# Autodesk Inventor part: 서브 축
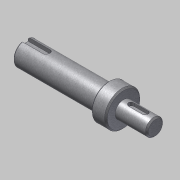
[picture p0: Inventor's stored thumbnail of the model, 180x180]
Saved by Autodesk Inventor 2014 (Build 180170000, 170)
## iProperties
Created: 2016-04
Part Number: 서브 축
Document SubType Name: Modeling
Designer: mdu
Density: 1 g/cm^3
Mass: 19.9624 g
Surface Area: 57.7178 cm^2
Volume: 19.9624 cm^3
Material: 강철, 연강
Appearance: 금속-강(스테인리스, 브러시됨)
Author: mdu
Revision Number: 1
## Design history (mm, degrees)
sketch "스케치1"
  geometry: L1 (-16.331, 0)-(-108.831, 0); L2 (-16.331, 0)-(-16.331, -6); L3 (-16.331, -6)-(-38.831, -6); L4 (-38.831, -12.5)-(-46.5, -12.5); L5 (-46.5, -8.5)-(-108.831, -8.5); L6 (-108.831, -8.5)-(-108.831, 0); L7 (-46.5, -8.5)-(-46.5, -12.5); L8 (-38.831, -6)-(-38.831, -12.5); L9 (-46.5, 12.249)-(-46.5, -12.249) reference; L10 (-38.831, -17)-(-38.831, 17) reference; 2 further points
  constraints: 17 end point, 4 perpendicular, 2 collinear, 2 parallel, 1 horizontal, 1 midpoint, 1 point on line
  dimensions: "d1" = 12 diameter of L3 L1; "d2" = 25 diameter of L4 L1; "d3" = 17 diameter of L5 L1; "d18" = 22.5 distance of L2.end L3.end; "d20" = 70 distance between parallel lines of L6 L8; "d21" = 7.66872 distance of L4.start L4.end (derived)
revolve "회전1" sketch "스케치1" stored, may be unused: angle "d5" = 90 deg
chamfer "모따기1" distance "d6" = 1; stored, may be unused: second distance "d7" = 2, angle "d8" = 45 deg
node "작업 평면1"
sketch "스케치2"
  geometry: L1 (11.25, 5)-(11.25, -5) reference; L2 (-5.75, -2)-(4.25, -2); L3 (4.25, 2)-(-5.75, 2); A1 r 2 centre (4.25, 0) between (4.25, -2) and (4.25, 2); A2 r 2 centre (-5.75, 0) between (-5.75, 2) and (-5.75, -2); 2 further points
  constraints: 4 end point, 4 point on circle, 4 tangent, 2 centre point, 1 horizontal alignment, 1 midpoint, 1 parallel, 1 perpendicular
  dimensions: "d9" = 4 distance between parallel lines of L2 L3; "d10" = 14 dimension on A1 A2; "d11" = 5 distance edge to line of A1 L1
extrude "돌출1" cut sketch "스케치2" distance "d12" = 2.5; taper "d13" = 0 deg
node "작업 평면2"
sketch "스케치3"
  geometry: L1 (-31.166, -7.5)-(-31.166, 7.5) reference; L2 (-31.166, 2.5)-(-15.666, 2.5); L3 (-15.666, -2.5)-(-31.166, -2.5); A1 r 2.5 centre (-15.666, 0) between (-15.666, -2.5) and (-15.666, 2.5); 2 further points
  constraints: 4 end point, 2 perpendicular, 2 point on circle, 2 point on line, 2 tangent, 1 centre point, 1 horizontal alignment, 1 midpoint
  dimensions: "d14" = 5 distance between parallel lines of L3 L2; "d15" = 18 dimension on A1 L1
extrude "돌출2" cut sketch "스케치3" distance "d16" = 3; taper "d17" = 0 deg
sketch "스케치4"
  geometry: C1 r 12.5 at (0, 0) reference; 1 further point
extrude "돌출3" join sketch "스케치4" distance "d22" = 3; taper "d23" = 0 deg
chamfer "모따기2" distance "d24" = 1; stored, may be unused: second distance "d25" = 2, angle "d26" = 45 deg
node "솔리드1"
node "참조4"
node "참조5"
